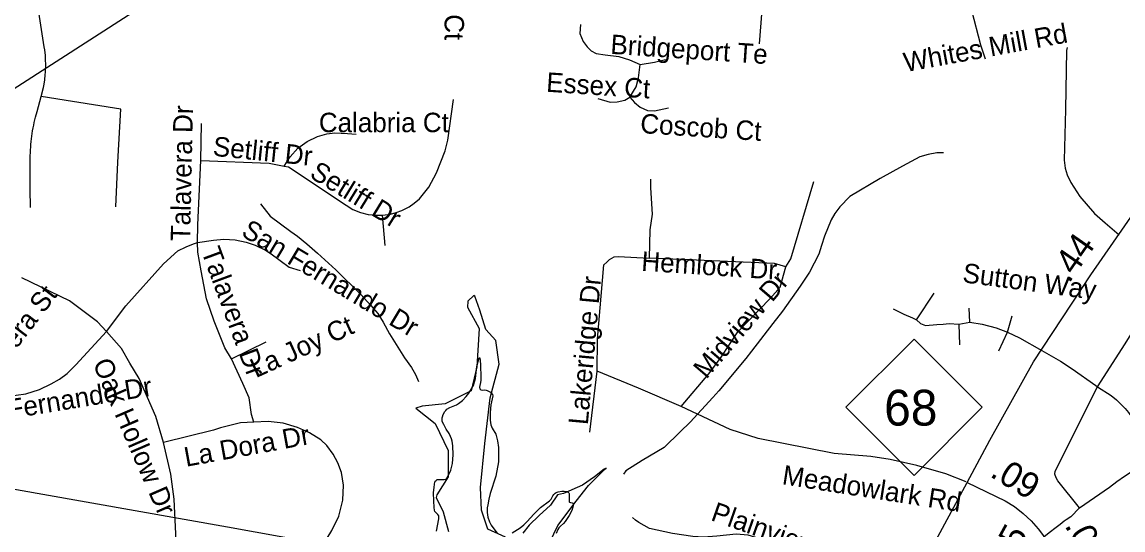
# Model space of a CAD drawing. Extents: x 1662474 to 1856135, y 779280 to 917889.
# Drawn here: x 1707785 to 1713168, y 829158 to 831640 of the extents above; entities that cross this region are included whole.
import ezdxf

# ---------------------------------------------------------------- set-up
doc = ezdxf.new("R2010")
doc.units = 0
for name, color, linetype in [('Exist Hydrographic Lake Shore', 7, 'Continuous'), ('Exist Hydrographic Misc Water Feature', 7, 'Continuous'), ('Exist Road Non-System Type 51', 7, 'Continuous'), ('Exist Road Non-System Type 51 Label', 7, 'Continuous'), ('Exist Road Primary NC Shield CELL', 7, 'Continuous'), ('Exist Road Primary NC Shield Number Label', 7, 'Continuous'), ('Exist Road Primary NC UnDivided 4 Lane Attributed', 7, 'Continuous'), ('Exist Road Secondary Mileage Tenths English Label', 7, 'Continuous'), ('Exist Road Secondary Type 51 Attributed', 7, 'Continuous'), ('Exist Utilities Electrical Transmission Line', 7, 'Continuous'), ('Old_Level_44', 7, 'Continuous'), ('Prop DGN Element Guardrail', 7, 'Continuous'), ('Prop Guardrail', 7, 'Continuous')]:
    doc.layers.add(name, color=color, linetype=linetype)

msp = doc.modelspace()

# ---------------------------------------------------------------- linework, layer by layer
at = {"layer": 'Exist Hydrographic Lake Shore'}
for points in [[(1709812.1, 829151.9), (1709822.6, 829212.6), (1709823.1, 829222.8), (1709822.1, 829227.2), (1709817.4, 829234.1), (1709807.9, 829243.2), (1709804, 829248.2), (1709801.4, 829254), (1709799.2, 829267.4), (1709797.8, 829301), (1709797.1, 829339.8), (1709799.2, 829366.9), (1709804, 829393.6), (1709804.8, 829395.8), (1709809.5, 829400.4), (1709815.2, 829403.9), (1709827.9, 829404.9), (1709848.1, 829403.9), (1709857, 829406.2), (1709860.4, 829408.6), (1709863.6, 829412.5), (1709880.9, 829449.6), (1709889.5, 829482.1), (1709893.5, 829525.1), (1709890.6, 829569.2), (1709887.5, 829592.1), (1709884.6, 829603.3), (1709880.6, 829614.6), (1709872.8, 829629.9), (1709859.4, 829650.9), (1709846.5, 829672.6), (1709839.1, 829687.9), (1709839.4, 829705.9), (1709840.5, 829711.5), (1709844.1, 829721.7), (1709851.8, 829736.4), (1709856.5, 829742.4), (1709862.2, 829747.7), (1709875.9, 829755.8), (1709908.5, 829770), (1709918.8, 829775.8), (1709938.4, 829791.2), (1709956.2, 829809.4), (1709970.1, 829826.9), (1709978.2, 829840.1), (1709993.2, 829867.9), (1709994.2, 829870), (1709999.2, 829886), (1710001.6, 829897.6), (1710009, 829956.9), (1710020.5, 829999.7), (1710022.9, 829998.9), (1710026.9, 829968.4), (1710028.6, 829899.4), (1710028.6, 829889.9), (1710027.1, 829879.2), (1710022.9, 829863.4), (1710021.9, 829855.3), (1710023.4, 829847.4), (1710025.8, 829844), (1710028.9, 829842.4), (1710035.8, 829841.4), (1710048.1, 829842.2), (1710054.1, 829841.9), (1710059.1, 829840.1), (1710076.1, 829831.4), (1710085.6, 829819.4), (1710086.4, 829813.1), (1710076.4, 829769.5), (1710074.6, 829732.2), (1710074.4, 829695.2), (1710075.4, 829683.6), (1710077.8, 829672.1), (1710084.2, 829655.3), (1710101.4, 829625.4), (1710110.5, 829593.1), (1710114.8, 829561.1), (1710114.2, 829490.2), (1710101.6, 829421.2), (1710073.5, 829335.9), (1710067, 829308.1), (1710061.8, 829280.2), (1710059.9, 829265.6), (1710059.4, 829243.2), (1710062.5, 829220.7), (1710070.1, 829197.3), (1710078.5, 829181.1), (1710086.6, 829169.8), (1710107.4, 829143)], [(1710181.4, 829143.5), (1710220.5, 829168.9), (1710238.4, 829183.4), (1710254.9, 829199.7), (1710286.6, 829235.4), (1710320.8, 829268.4), (1710364.4, 829300.4), (1710371.5, 829309.1), (1710380.1, 829324.3), (1710385.1, 829331.4), (1710391.6, 829337.8), (1710397.4, 829341.1), (1710406.9, 829344.3), (1710423.9, 829347.2), (1710436, 829347.4), (1710447.9, 829345.9), (1710450.5, 829345.1), (1710454.6, 829342.4), (1710457, 829340.4), (1710458, 829339.1), (1710460.1, 829335.9), (1710459.9, 829295.8), (1710461.8, 829294.2), (1710466.5, 829292.6), (1710474.6, 829291), (1710477.8, 829289.7), (1710479.2, 829287.3), (1710480.1, 829276.6), (1710472.8, 829253.5), (1710460.1, 829229.3), (1710441, 829198.9), (1710432.1, 829189.2), (1710417.1, 829175.8), (1710410.2, 829168.7), (1710405, 829160.6), (1710396.9, 829140.9)]]:
    msp.add_lwpolyline(points, dxfattribs=at)
at = {"layer": 'Exist Hydrographic Misc Water Feature'}
for points in [[(1712290, 831000.2), (1712258, 831000), (1712216, 830992.7), (1712175.7, 830980.4), (1712089.4, 830935.3), (1711981, 830875.2), (1711832.3, 830787.9), (1711784.1, 830736.4), (1711759.8, 830704.1), (1711741.7, 830674.1), (1711709.2, 830594.3), (1711694.8, 830548.6), (1711680.7, 830506.3), (1711636.2, 830417), (1711589.9, 830348.9), (1711503.1, 830227.6), (1711456.9, 830167), (1711351.9, 830032.1), (1711323.6, 829995.8), (1711192.5, 829838.4), (1711162.3, 829804.6), (1711051.6, 829685.4), (1711003.5, 829637.1), (1710925, 829561.6), (1710888.9, 829539.3), (1710852.5, 829517.9), (1710816.5, 829498.1), (1710738, 829446.4), (1710725.8, 829430.2)], [(1708950.2, 830751.4), (1708998.1, 830691.4), (1709099.7, 830616.3), (1709131.7, 830594.3), (1709177.7, 830556.4), (1709229.2, 830510.2), (1709319.1, 830429.6), (1709440.6, 830308.9), (1709490.5, 830254.7), (1709524.1, 830216.2), (1709550.1, 830173.8), (1709581.8, 830115.7), (1709655.4, 829999.3), (1709689, 829951.1), (1709709.1, 829917), (1709722.8, 829883)]]:
    msp.add_lwpolyline(points, dxfattribs=at)
at = {"layer": 'Exist Road Non-System Type 51'}
for p, q in [((1711390.4, 831533.5), (1711411.9, 831804.9)), ((1708659.6, 830963.2), (1708662.9, 831144.5)), ((1709559.9, 830547.7), (1709548.1, 830695.9)), ((1712158, 830184.4), (1712245.1, 830315.1)), ((1712419.6, 830173.1), (1712416.2, 830242.2)), ((1712602.9, 830125.1), (1712626.8, 830204.4)), ((1712365.6, 830163.7), (1712419.6, 830173.1)), ((1712365.6, 830163.7), (1712368.5, 830061.9)), ((1712560.6, 830033.8), (1712602.9, 830125.1)), ((1708808.8, 829993.4), (1708978.5, 830077.6)), ((1710561.4, 829635.6), (1710597.9, 829934.6))]:
    msp.add_line(p, q, dxfattribs=at)
for points in [[(1707877.8, 831275.8), (1707888.8, 831319.4), (1707890.6, 831328.2), (1707895.4, 831355.8), (1707898.2, 831383.6), (1707899, 831392.5), (1707899.9, 831402), (1707900.6, 831430.1), (1707900.6, 831439.5), (1707900.1, 831448.7), (1707898.8, 831476.8), (1707895.6, 831504.4), (1707893.5, 831518.2), (1707866.8, 831688.6), (1707859.4, 831737.2), (1707855.1, 831790.7), (1707871.1, 831855)], [(1712495.5, 831458.7), (1712473.9, 831527.2), (1712428.9, 831696.2), (1712420.5, 831737.4), (1712416.2, 831842.1)], [(1710515.2, 831627.4), (1710513.1, 831583.6), (1710528.6, 831545), (1710547.5, 831519), (1710568.5, 831499.1), (1710592.4, 831486.8), (1710635.8, 831480.4), (1710702.9, 831471.8), (1710755.9, 831455.2), (1710780.9, 831443.7), (1710808.1, 831431.7)], [(1712895.5, 831516.1), (1712892.9, 831501.4), (1712887.5, 831211.9), (1712880.8, 830965.4), (1712885.2, 830925.2), (1712895.5, 830893), (1712914.1, 830855.2), (1712957.9, 830786.7), (1713029.4, 830704), (1713081.9, 830658.4), (1713149.9, 830599.4)], [(1710757, 831272.4), (1710788.2, 831323.2), (1710799.8, 831367.9), (1710808.1, 831431.7)], [(1710808.1, 831431.7), (1710878, 831443.2), (1710931, 831456.6)], [(1707825.5, 830733.2), (1707824.8, 830823.2), (1707825.2, 830974.4), (1707825.2, 830988.1), (1707825.5, 831001.2), (1707826.1, 831015.1), (1707827.1, 831028.5), (1707827.9, 831042.2), (1707829.2, 831055.5), (1707830.8, 831068.9), (1707834.5, 831095.9), (1707836.6, 831108.9), (1707838.9, 831122.4), (1707841.6, 831135.6), (1707844.6, 831148.9), (1707847.6, 831162.1), (1707851, 831174.9), (1707859.1, 831202.5), (1707877.8, 831275.8)], [(1708243.9, 830736.4), (1708253.9, 830954.5), (1708268.1, 831214.6), (1708030.8, 831251.1), (1707877.8, 831275.8)], [(1710599.8, 831266.9), (1710661.4, 831248.4), (1710694.5, 831249.2), (1710733.1, 831258.7), (1710757, 831272.4)], [(1710757, 831272.4), (1710779.9, 831246.1), (1710808.1, 831223.2), (1710843.4, 831208.2), (1710877.8, 831206.7), (1710945.4, 831220.1)], [(1709548.1, 830695.9), (1709585.9, 830701.2), (1709614.8, 830708.6), (1709642.6, 830719.4), (1709677.8, 830737.4), (1709702.1, 830754.5), (1709727.6, 830776.8), (1709773.5, 830832.4), (1709811.6, 830902.5), (1709853.6, 831010.7), (1709867.2, 831063.4), (1709894, 831262.1)], [(1709067, 830936.1), (1709095.1, 830981.5), (1709133.1, 831023), (1709178.5, 831056.4), (1709229.8, 831081), (1709274.4, 831093.4), (1709315, 831097.8), (1709376.6, 831094.7), (1709419.2, 831091.5)], [(1708642.1, 830562.1), (1708644.1, 830649.5), (1708659.6, 830963.2)], [(1708659.6, 830963.2), (1708992.6, 830949.8), (1709067, 830936.1)], [(1709067, 830936.1), (1709087.4, 830932.4), (1709368.9, 830744.5), (1709402.9, 830724.6), (1709439.6, 830709.6), (1709478, 830699.9), (1709517.4, 830695.4), (1709548.1, 830695.9)], [(1713044.6, 829857.9), (1713179.2, 830068.2), (1713282.9, 830234.5), (1713371.1, 830371.2), (1713408.4, 830434.2), (1713449.6, 830504.4), (1713497.6, 830553.2), (1713568.5, 830616.9), (1713628.4, 830659.5), (1713727, 830714.1), (1713813.6, 830757.1), (1713962.4, 830814.6), (1714085.8, 830846.1), (1714271.4, 830905.7)], [(1710852.5, 830486), (1710855.6, 830624), (1710868.2, 830700.7), (1710859.4, 830830.1), (1710859.4, 830872.6)], [(1711520.5, 830444.5), (1711543.6, 830482.6), (1711657, 830860.8)], [(1708642.1, 830562.1), (1708721.1, 830574.4), (1708771.4, 830579.2), (1708826.4, 830575.5), (1708879.9, 830565), (1708925.2, 830549.8), (1708974.4, 830525.6), (1709003.1, 830507), (1709090.9, 830441.6), (1709144.1, 830425.6)], [(1708198, 830127.2), (1708292.8, 830253.7), (1708476.4, 830458.9), (1708546.2, 830521.7), (1708588, 830541.1), (1708622.4, 830555.8), (1708642.1, 830562.1)], [(1708808.8, 829993.4), (1708776.4, 830047.4), (1708723.4, 830177.6), (1708687.1, 830287.9), (1708660.1, 830424.9), (1708645.1, 830516.2), (1708642.1, 830562.1)], [(1710597.9, 829934.6), (1710598.8, 830091), (1710629.9, 830453.2), (1710645.1, 830466.2), (1710658, 830480.2), (1710680.6, 830492), (1710700, 830494.1), (1710852.5, 830486)], [(1711520.5, 830444.5), (1711463.8, 830460.2), (1710852.5, 830486)], [(1711007.6, 829761.6), (1711142.5, 829920.7), (1711203.4, 830002.5), (1711285.1, 830126.9), (1711442.5, 830288.6), (1711491.4, 830345), (1711520.5, 830444.5)], [(1708198, 830127.2), (1708153.1, 830175.8), (1708016.4, 830277.9), (1707783.2, 830389.7)], [(1712044.6, 830238.8), (1712096.6, 830213), (1712138.6, 830195.2), (1712158, 830184.4)], [(1712158, 830184.4), (1712177.9, 830166.9), (1712201.9, 830157.7), (1712258.5, 830161.4), (1712289.5, 830164.2), (1712319.1, 830166.6), (1712365.6, 830163.7)], [(1712419.6, 830173.1), (1712480.1, 830162.9), (1712548.6, 830146.4), (1712602.9, 830125.1)], [(1707465.6, 829896.8), (1707527.9, 829857.9), (1707580.9, 829836.1), (1707636.4, 829823.8), (1707691.4, 829816.2), (1707731.6, 829814.6), (1707755.8, 829816.2), (1707803.8, 829822.8), (1707870.6, 829844.2), (1707926.9, 829871.9), (1707967.5, 829894.4), (1708005.1, 829922.8), (1708047.6, 829964.2), (1708198, 830127.2)], [(1708476.1, 829586), (1708438.4, 829712), (1708357, 829897.5), (1708312.1, 829973.4), (1708271.5, 830044.8), (1708198, 830127.2)], [(1712602.9, 830125.1), (1712663, 830097.5), (1712772.1, 830035.4)], [(1712772.1, 830035.4), (1712862.8, 829983.1), (1712919.9, 829945.6), (1713035.9, 829863.7), (1713044.6, 829857.9)], [(1708917.4, 829684.9), (1708907.1, 829722.5), (1708894.6, 829803.9), (1708864.4, 829874.4), (1708808.8, 829993.4)], [(1711007.6, 829761.6), (1710800, 829850.9), (1710597.9, 829934.6)], [(1712955.9, 829265.5), (1712849.6, 829398.1), (1712841.1, 829412.5), (1712835.1, 829430.6), (1712836.1, 829444.8), (1713044.6, 829857.9)], [(1713044.6, 829857.9), (1713111.2, 829815.4), (1713137.2, 829793.9), (1713161.4, 829770.2), (1713178.9, 829751.6), (1713194.8, 829731.7), (1713209.9, 829711.2), (1713223.9, 829689.9), (1713240.6, 829660.5), (1713251.9, 829637.4), (1713262.1, 829614.1), (1713271.1, 829590.4), (1713278.4, 829566.4), (1713284.8, 829541.4), (1713289.8, 829516.7), (1713297.4, 829488.4)], [(1712401.4, 829392.9), (1712302.4, 829432.2), (1712160.1, 829472.9), (1712029.4, 829502.9), (1711935.9, 829516.4), (1711755.4, 829530.9), (1711385.1, 829605.7), (1711247.2, 829649.5), (1711007.6, 829761.6)], [(1708917.4, 829684.9), (1708853.4, 829680.8), (1708755.4, 829657.4), (1708720.5, 829645.9), (1708476.1, 829586)], [(1709146, 828982.6), (1709209.2, 829035.1), (1709259.4, 829089.2), (1709298.8, 829154.8), (1709333.1, 829225.9), (1709352.9, 829303.6), (1709357, 829377.6), (1709347.6, 829439), (1709328.9, 829486), (1709306.1, 829529), (1709274.9, 829570.5), (1709245.8, 829598.1), (1709190.9, 829632.8), (1709131.6, 829659.2), (1709061.2, 829679.2), (1708989, 829687.6), (1708917.4, 829684.9)], [(1708527.9, 828934), (1708537.4, 829139), (1708528.9, 829308.9), (1708512.1, 829429.9), (1708476.1, 829586)], [(1712955.9, 829265.5), (1713101.9, 829366.9), (1713138, 829394.7), (1713175.4, 829420.9), (1713214.1, 829445.1), (1713254.4, 829467.1), (1713297.4, 829488.4)], [(1712123.1, 828849.8), (1711726.2, 829000.4), (1711490.6, 829085.2), (1711335.6, 829132.2), (1711276.9, 829137.7), (1711182.4, 829127.5), (1711116.6, 829123.2), (1711064.6, 829126.4), (1710965.4, 829140.9), (1710853.4, 829165.5), (1710801.1, 829193.9), (1710783.9, 829205.6), (1710769.6, 829218.9)], [(1712955.9, 829265.5), (1712913.1, 829222.5), (1712890.5, 829207.8), (1712886.2, 829204.9), (1712880, 829200.7), (1712860.6, 829184.4), (1712835.6, 829165.5), (1712814.1, 829148.2), (1712791.9, 829130.9), (1712774.5, 829117.8), (1712771.1, 829115.2)]]:
    msp.add_lwpolyline(points, dxfattribs=at)
at = {"layer": 'Exist Road Primary NC Shield CELL'}
msp.add_lwpolyline([(1711813.5, 829757.7), (1712146.5, 830090.7), (1712479.5, 829757.7), (1712146.5, 829424.7)], close=True, dxfattribs=at)
at = {"layer": 'Exist Road Primary NC UnDivided 4 Lane Attributed'}
for points in [[(1712406.1, 829389.5), (1712517.7, 829596.8), (1712730.8, 829980.1), (1713011.4, 830404.2), (1713233.4, 830723.7), (1713693, 831349)], [(1711731.2, 828110.9), (1711903.3, 828436.8), (1712177.1, 828964.1), (1712406.1, 829389.5)]]:
    msp.add_lwpolyline(points, dxfattribs=at)
at = {"layer": 'Exist Road Secondary Type 51 Attributed'}
msp.add_lwpolyline([(1712406.1, 829389.5), (1712592.9, 829300.4), (1712637.2, 829273.5), (1712681.1, 829238.9), (1712718.6, 829202.9), (1712753.7, 829163.9), (1712784.9, 829122.4)], dxfattribs=at)
at = {"layer": 'Exist Utilities Electrical Transmission Line'}
for points in [[(1704330.5, 829125.1), (1704357.7, 829137.4), (1704549.9, 829219.5), (1704987.4, 829509.1), (1705656.6, 829944.3), (1706235.2, 830322.3), (1706743.5, 830657.3), (1707181, 830946.8), (1707763.6, 831326.9), (1708303.7, 831673.4), (1708928.7, 832081.1), (1709620.3, 832536.3), (1710291.6, 832975.4), (1711027.5, 833455.9), (1711648.5, 833863.6), (1712239.1, 834253.8), (1713005.3, 834756), (1713847.9, 835307.5)], [(1704330.5, 829125.1), (1704363.9, 829125.2), (1704441.7, 829122.8), (1704707.5, 829163.8), (1705527.8, 829317.2), (1706167.7, 829434.6), (1706717.3, 829530.9), (1706941.1, 829496.5), (1707139, 829464.5), (1707886.3, 829332.6), (1708789.5, 829173.1), (1709700.6, 829009.5), (1710597.6, 828852.2), (1711504.6, 828682.4), (1712417.9, 828528.9), (1713335, 828365.2)]]:
    msp.add_lwpolyline(points, dxfattribs=at)
at = {"layer": 'Old_Level_44'}
for points in [[(1710149.2, 829123), (1710062.8, 829161.4), (1710031.8, 829254.5), (1710026, 829365), (1710047.2, 829580.7), (1710073.7, 829803.5), (1710118.5, 829967.7), (1710101.8, 830084.5), (1710053.1, 830138), (1710023.9, 830231.5), (1709998.1, 830300.2), (1709994.8, 830303.2), (1709965.3, 830275.6), (1709963, 830246.6), (1710020, 830143.1), (1710008.3, 829955.9), (1709980.4, 829837.3), (1709853.9, 829774.1), (1709740.7, 829763.3), (1709711, 829753.4), (1709805.4, 829678), (1709868.4, 829545.8), (1709868.4, 829418.2), (1709812.6, 829329), (1709809.4, 829316.3), (1709844.2, 829246.7), (1709870, 829149.9)], [(1710326, 829017.4), (1710404.7, 829180.4), (1710495.2, 829299.5), (1710554.7, 829375.2), (1710633.1, 829453.6), (1710641.8, 829459.8), (1710631.2, 829455.3), (1710583.8, 829417.4), (1710525.8, 829376.8), (1710432.5, 829336), (1710402.5, 829329.3), (1710369.5, 829279.9), (1710313.4, 829229.4), (1710264.7, 829180.7), (1710233.5, 829141.7)]]:
    msp.add_lwpolyline(points, dxfattribs=at)

# ---------------------------------------------------------------- texts
at = {"layer": 'Exist Road Non-System Type 51 Label'}
for s, rotation, p in [('Mill Wheel Ct', 270, (1709850.9, 832299.1)), ('Whites Mill Rd', 10.3816, (1712105.1, 831394.8)), ('Bridgeport Te', 356.2442, (1710660, 831484.6)), ('Essex Ct', 356.2442, (1710346.2, 831299.6)), ('Talavera Dr', 88.7553, (1708606.3, 830567.7)), ('Coscob Ct', 356.2442, (1710805.7, 831097.7)), ('Setliff Dr', 354.1254, (1708714.7, 830986.9)), ('Setliff Dr', 328.5454, (1709185.4, 830884.1)), ('San Fernando Dr', 329.0222, (1708851.3, 830598.6)), ('Talavera Dr', 290.2333, (1708660, 830520.3)), ('Hemlock Dr', 356.2442, (1710811.3, 830424.8)), ('Sutton Way', 352.4334, (1712380.2, 830368.9)), ('Midview Dr', 49.4822, (1711131.5, 829891.7)), ('Lavera St', 52.6103, (1707631.3, 829875.2)), ('Lakeridge Dr', 84.8273, (1710551.3, 829668.9)), ('La Joy Ct', 24.5708, (1708928.1, 829899.2)), ('Oak Hollow Dr', 293.4171, (1708128.8, 829972.2)), ('San Fernando Dr', 9.2915, (1707464, 829658)), ('La Dora Dr', 10.3364, (1708586.6, 829466.6)), ('Meadowlark Rd', 351.124, (1711497.8, 829381.9)), ('Plainview Dr', 340.6326, (1711148.1, 829207))]:
    msp.add_text(s, height=95, rotation=rotation, dxfattribs=at).set_placement(p)
msp.add_text('Calabria Ct', height=95, dxfattribs=at).set_placement((1709236.2, 831101.7))
at = {"layer": 'Exist Road Primary NC Shield Number Label'}
msp.add_text('68', height=175, dxfattribs=at).set_placement((1712000.6, 829668))
at = {"layer": 'Exist Road Secondary Mileage Tenths English Label'}
msp.add_text('.05', height=125, rotation=61.2436, dxfattribs=at).set_placement((1712595.1, 828934.7))
at = {"layer": 'Prop DGN Element Guardrail'}
for s, rotation, p in [('.09', 328.8514, (1712512.7, 829421.8)), ('.02', 298.8698, (1712881.2, 829180.1))]:
    msp.add_text(s, height=125, rotation=rotation, dxfattribs=at).set_placement(p)
at = {"layer": 'Prop Guardrail'}
msp.add_text('.44', height=125, rotation=55.2037, dxfattribs=at).set_placement((1712904.3, 830359.5))

doc.saveas('drawing.dxf')
